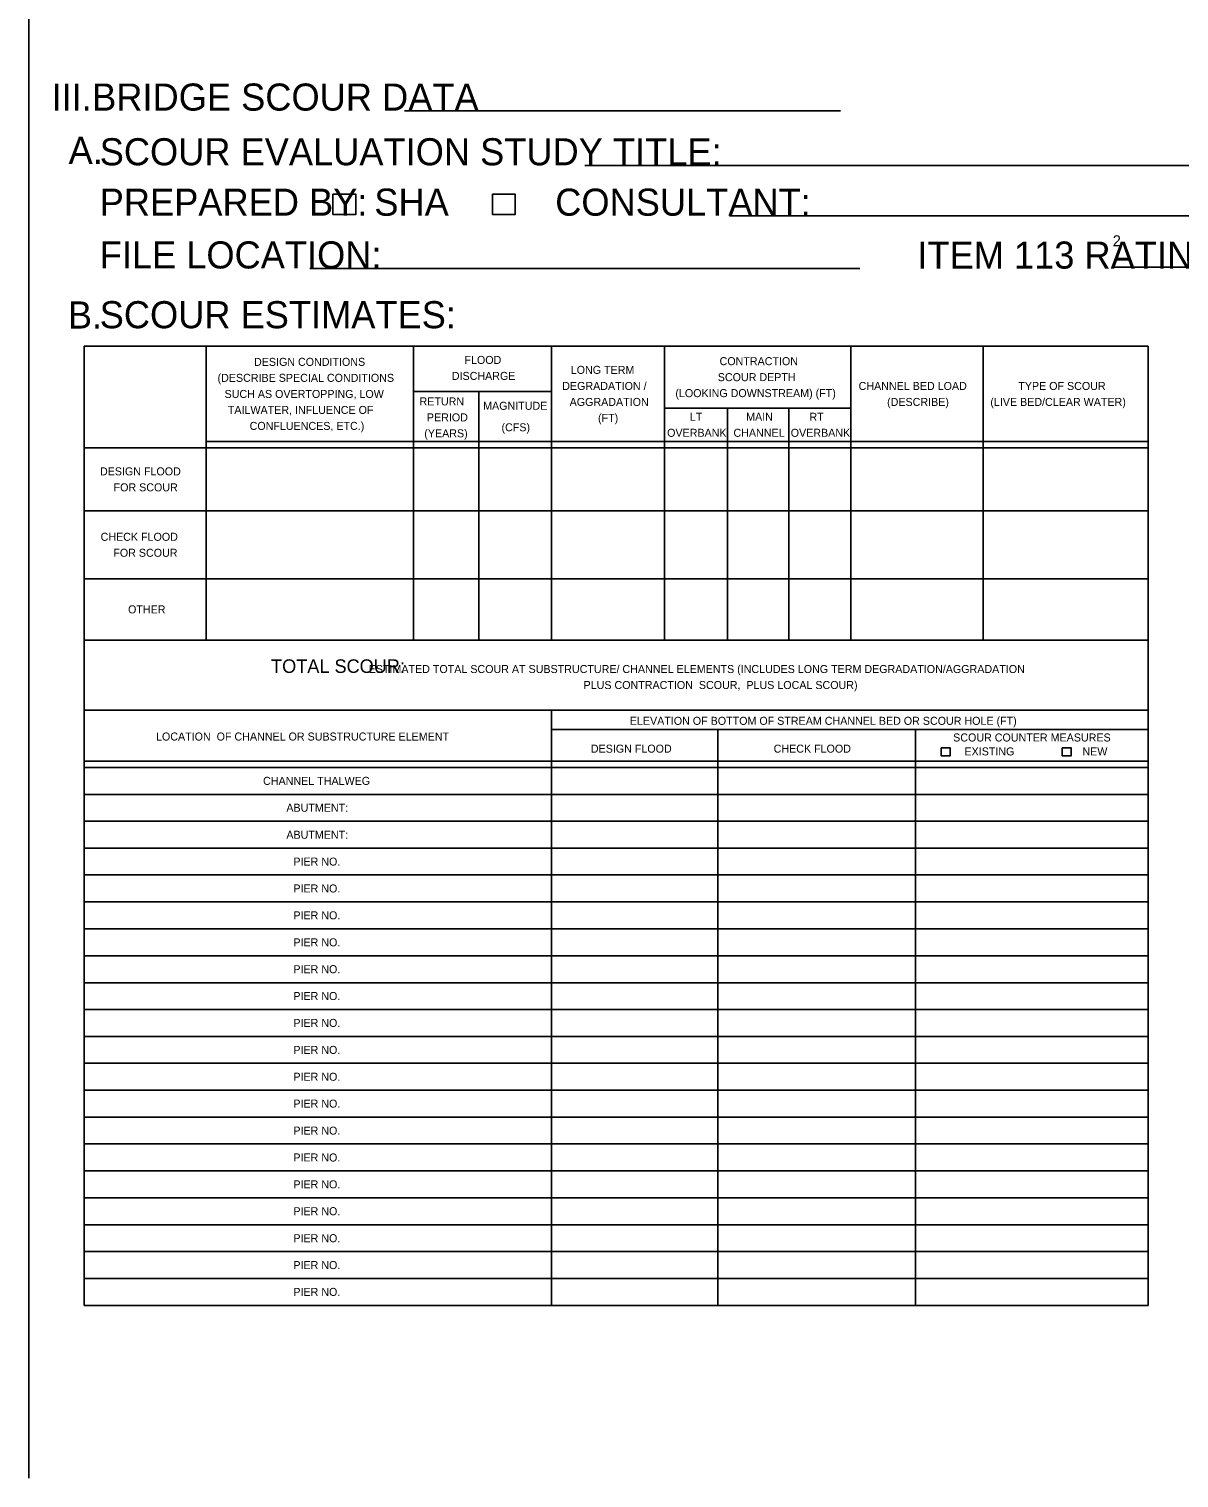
# Model space of a CAD drawing. Extents: x 2.9 to 32.9, y 0.8 to 21.2.
# Drawn here: x 12.34 to 20.69, y 0.75 to 11.27 of the extents above; entities that cross this region are included whole.
import ezdxf

# ---------------------------------------------------------------- set-up
doc = ezdxf.new("R2010")
doc.units = 0
doc.layers.add('G-ANNO-NOTE', color=7, linetype='Continuous')

msp = doc.modelspace()

# ---------------------------------------------------------------- linework, layer by layer
at = {"layer": 'G-ANNO-NOTE'}
for p, q in [((12.339, 21.185), (12.339, 0.75)), ((18.234, 10.676), (15.068, 10.676)), ((24.999, 10.279), (16.378, 10.279)), ((21.859, 10.279), (17.609, 10.279)), ((22.898, 9.913), (17.429, 9.913)), ((18.375, 9.53), (14.379, 9.53)), ((24.999, 9.541), (20.219, 9.541)), ((12.741, 8.967), (12.741, 8.967)), ((20.47, 8.967), (12.741, 8.967)), ((12.741, 2.003), (12.741, 8.967)), ((13.626, 6.833), (13.626, 8.967)), ((15.132, 6.833), (15.132, 8.967)), ((16.136, 6.833), (16.136, 8.967)), ((16.956, 6.833), (16.956, 8.967)), ((18.309, 6.833), (18.309, 8.967)), ((18.309, 8.967), (19.272, 8.967)), ((19.272, 6.833), (19.272, 8.967)), ((20.47, 2.003), (20.47, 8.967)), ((16.136, 8.638), (15.133, 8.638)), ((15.606, 6.833), (15.606, 8.638)), ((18.309, 8.518), (16.956, 8.518)), ((17.414, 6.833), (17.414, 8.518)), ((17.858, 6.833), (17.858, 8.518)), ((20.47, 8.228), (12.741, 8.228)), ((20.47, 8.274), (13.626, 8.274)), ((17.414, 8.293), (17.414, 8.299)), ((17.858, 8.293), (17.858, 8.299)), ((20.47, 7.771), (12.741, 7.771)), ((20.47, 7.279), (12.746, 7.279)), ((20.47, 6.833), (12.741, 6.833)), ((20.47, 6.325), (12.741, 6.325)), ((16.136, 2.003), (16.136, 6.325)), ((20.47, 6.184), (16.136, 6.184)), ((17.344, 2.003), (17.344, 6.185)), ((18.779, 2.003), (18.779, 6.178)), ((20.47, 5.954), (12.741, 5.954)), ((20.47, 5.909), (12.741, 5.909)), ((20.47, 5.909), (12.741, 5.909)), ((20.47, 5.713), (12.741, 5.713)), ((20.47, 5.518), (12.741, 5.518)), ((20.47, 5.323), (12.741, 5.323)), ((20.47, 5.128), (12.741, 5.128)), ((20.47, 4.932), (12.741, 4.932)), ((20.47, 4.737), (12.741, 4.737)), ((20.47, 4.542), (12.741, 4.542)), ((20.47, 4.346), (12.741, 4.346)), ((20.47, 4.151), (12.741, 4.151)), ((20.47, 3.956), (12.741, 3.956)), ((20.47, 3.761), (12.741, 3.761)), ((20.47, 3.565), (12.741, 3.565)), ((20.47, 3.37), (12.741, 3.37)), ((20.47, 3.175), (12.741, 3.175)), ((20.47, 2.98), (12.741, 2.98)), ((20.47, 2.784), (12.741, 2.784)), ((20.47, 2.589), (12.741, 2.589)), ((20.47, 2.394), (12.741, 2.394)), ((20.47, 2.198), (12.741, 2.198)), ((20.47, 2.003), (12.741, 2.003))]:
    msp.add_line(p, q, dxfattribs=at)
for points in [[(14.547, 10.07), (14.714, 10.07), (14.714, 9.924), (14.547, 9.924)], [(15.706, 10.07), (15.872, 10.07), (15.872, 9.924), (15.706, 9.924)], [(18.966, 6.052), (19.03, 6.052), (19.03, 5.992), (18.966, 5.992)], [(19.845, 6.052), (19.909, 6.052), (19.909, 5.992), (19.845, 5.992)]]:
    msp.add_lwpolyline(points, close=True, dxfattribs=at)

# ---------------------------------------------------------------- texts
for s, height, p in [('III. ', 0.1968, (12.503, 10.677)), ('BRIDGE SCOUR DATA', 0.19685, (12.798, 10.677)), ('A. ', 0.1968, (12.627, 10.29)), ('SCOUR EVALUATION STUDY TITLE:', 0.19677, (12.853, 10.28)), ('PREPARED BY:', 0.19677, (12.853, 9.914)), ('SHA', 0.1968, (14.848, 9.914)), ('CONSULTANT:', 0.19677, (16.162, 9.914)), ('FILE LOCATION:', 0.19677, (12.853, 9.531)), ('ITEM 113 RATING', 0.19677, (18.793, 9.53)), ('2', 0.0797, (20.212, 9.692)), ('B. ', 0.1968, (12.622, 9.095)), ('SCOUR ESTIMATES:', 0.19677, (12.853, 9.097)), ('DESIGN CONDITIONS', 0.05811, (13.974, 8.824)), ('FLOOD', 0.0581, (15.503, 8.838)), ('CONTRACTION', 0.05811, (17.356, 8.829)), ('(DESCRIBE SPECIAL CONDITIONS', 0.05811, (13.709, 8.708)), ('DISCHARGE', 0.0581, (15.411, 8.722)), ('LONG TERM ', 0.0581, (16.275, 8.766)), ('SCOUR DEPTH', 0.05811, (17.343, 8.713)), ('SUCH AS OVERTOPPING, LOW', 0.05811, (13.76, 8.591)), ('DEGRADATION /', 0.05811, (16.213, 8.649)), ('(LOOKING DOWNSTREAM) (FT)', 0.05811, (17.035, 8.597)), ('CHANNEL BED LOAD', 0.05811, (18.366, 8.649)), ('TYPE OF SCOUR', 0.05811, (19.526, 8.649)), ('TAILWATER, INFLUENCE OF ', 0.05811, (13.784, 8.475)), (' RETURN ', 0.0581, (15.155, 8.537)), (' MAGNITUDE', 0.0581, (15.617, 8.505)), ('AGGRADATION', 0.05811, (16.267, 8.533)), ('(DESCRIBE)', 0.0581, (18.573, 8.533)), ('(LIVE BED/CLEAR WATER)', 0.05811, (19.323, 8.533)), ('CONFLUENCES, ETC.)', 0.05811, (13.942, 8.359)), ('PERIOD', 0.0581, (15.23, 8.421)), ('(FT)', 0.0581, (16.473, 8.417)), ('LT', 0.0581, (17.14, 8.425)), ('MAIN', 0.0581, (17.549, 8.425)), ('RT ', 0.0581, (18.009, 8.425)), ('(YEARS)', 0.0581, (15.211, 8.305)), ('(CFS)', 0.0581, (15.772, 8.349)), ('OVERBANK', 0.0581, (16.975, 8.309)), ('CHANNEL', 0.0581, (17.457, 8.309)), ('OVERBANK', 0.0581, (17.873, 8.309)), ('DESIGN FLOOD ', 0.05812, (12.855, 8.029)), ('FOR SCOUR', 0.0581, (12.954, 7.913)), (' CHECK FLOOD ', 0.05812, (12.838, 7.554)), ('FOR SCOUR', 0.0581, (12.952, 7.438)), ('OTHER', 0.0581, (13.059, 7.027)), ('TOTAL SCOUR:', 0.09839, (14.098, 6.595)), ('ESTIMATED TOTAL SCOUR AT SUBSTRUCTURE/ CHANNEL ELEMENTS (INCLUDES LONG TERM DEGRADATION/AGGRADATION ', 0.05811, (14.807, 6.594)), ('PLUS CONTRACTION  SCOUR,  PLUS LOCAL SCOUR)', 0.05811, (16.368, 6.478)), ('ELEVATION OF BOTTOM OF STREAM CHANNEL BED OR SCOUR HOLE (FT)', 0.05811, (16.704, 6.218)), ('LOCATION  OF CHANNEL OR SUBSTRUCTURE ELEMENT', 0.05812, (13.262, 6.104)), ('SCOUR COUNTER MEASURES', 0.05811, (19.053, 6.097)), ('DESIGN FLOOD', 0.05811, (16.421, 6.016)), ('CHECK FLOOD', 0.05811, (17.749, 6.016)), ('EXISTING', 0.0581, (19.135, 5.996)), ('NEW', 0.0581, (19.992, 5.996)), ('CHANNEL THALWEG', 0.05812, (14.04, 5.782)), ('ABUTMENT:', 0.0581, (14.209, 5.587)), ('ABUTMENT:', 0.0581, (14.209, 5.391)), ('PIER NO.', 0.0581, (14.26, 5.196)), ('PIER NO.', 0.0581, (14.26, 5.001)), ('PIER NO.', 0.0581, (14.26, 4.806)), ('PIER NO.', 0.0581, (14.26, 4.61)), ('PIER NO.', 0.0581, (14.26, 4.415)), ('PIER NO.', 0.0581, (14.26, 4.22)), ('PIER NO.', 0.0581, (14.26, 4.025)), ('PIER NO.', 0.0581, (14.26, 3.829)), ('PIER NO.', 0.0581, (14.26, 3.634)), ('PIER NO.', 0.0581, (14.26, 3.439)), ('PIER NO.', 0.0581, (14.26, 3.243)), ('PIER NO.', 0.0581, (14.26, 3.048)), ('PIER NO.', 0.0581, (14.26, 2.853)), ('PIER NO.', 0.0581, (14.26, 2.658)), ('PIER NO.', 0.0581, (14.26, 2.462)), ('PIER NO.', 0.0581, (14.26, 2.267)), ('PIER NO.', 0.0581, (14.26, 2.072))]:
    msp.add_text(s, height=height, dxfattribs=at).set_placement(p)

doc.saveas('drawing.dxf')
